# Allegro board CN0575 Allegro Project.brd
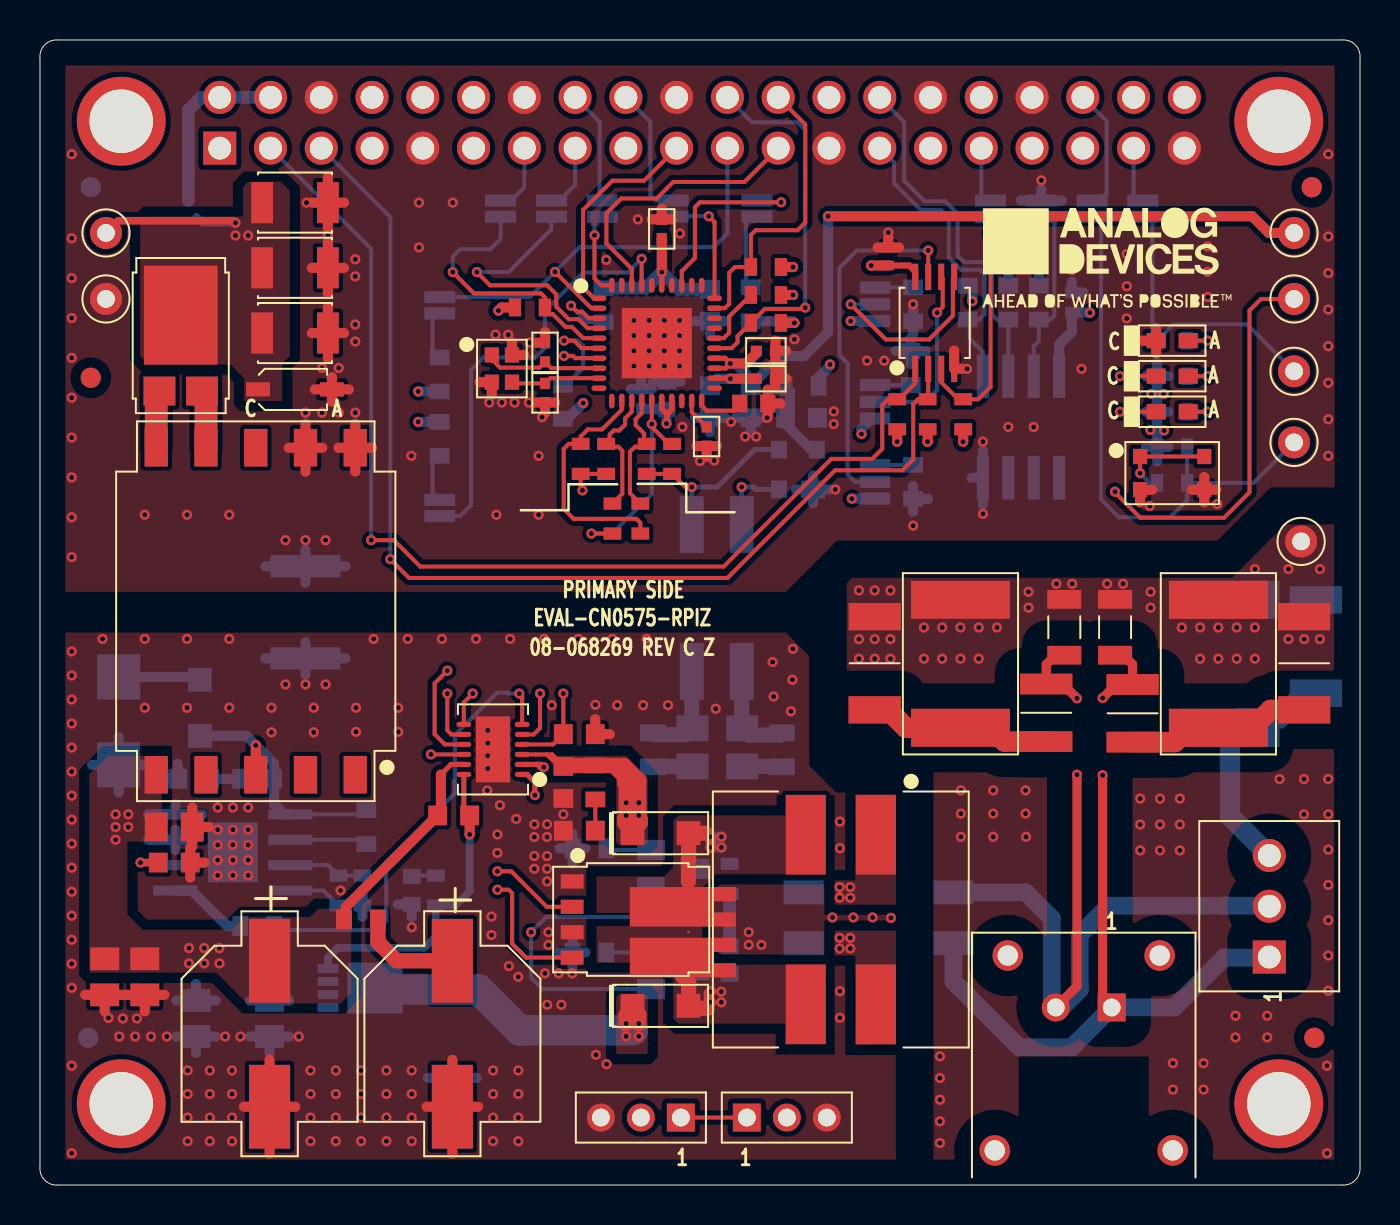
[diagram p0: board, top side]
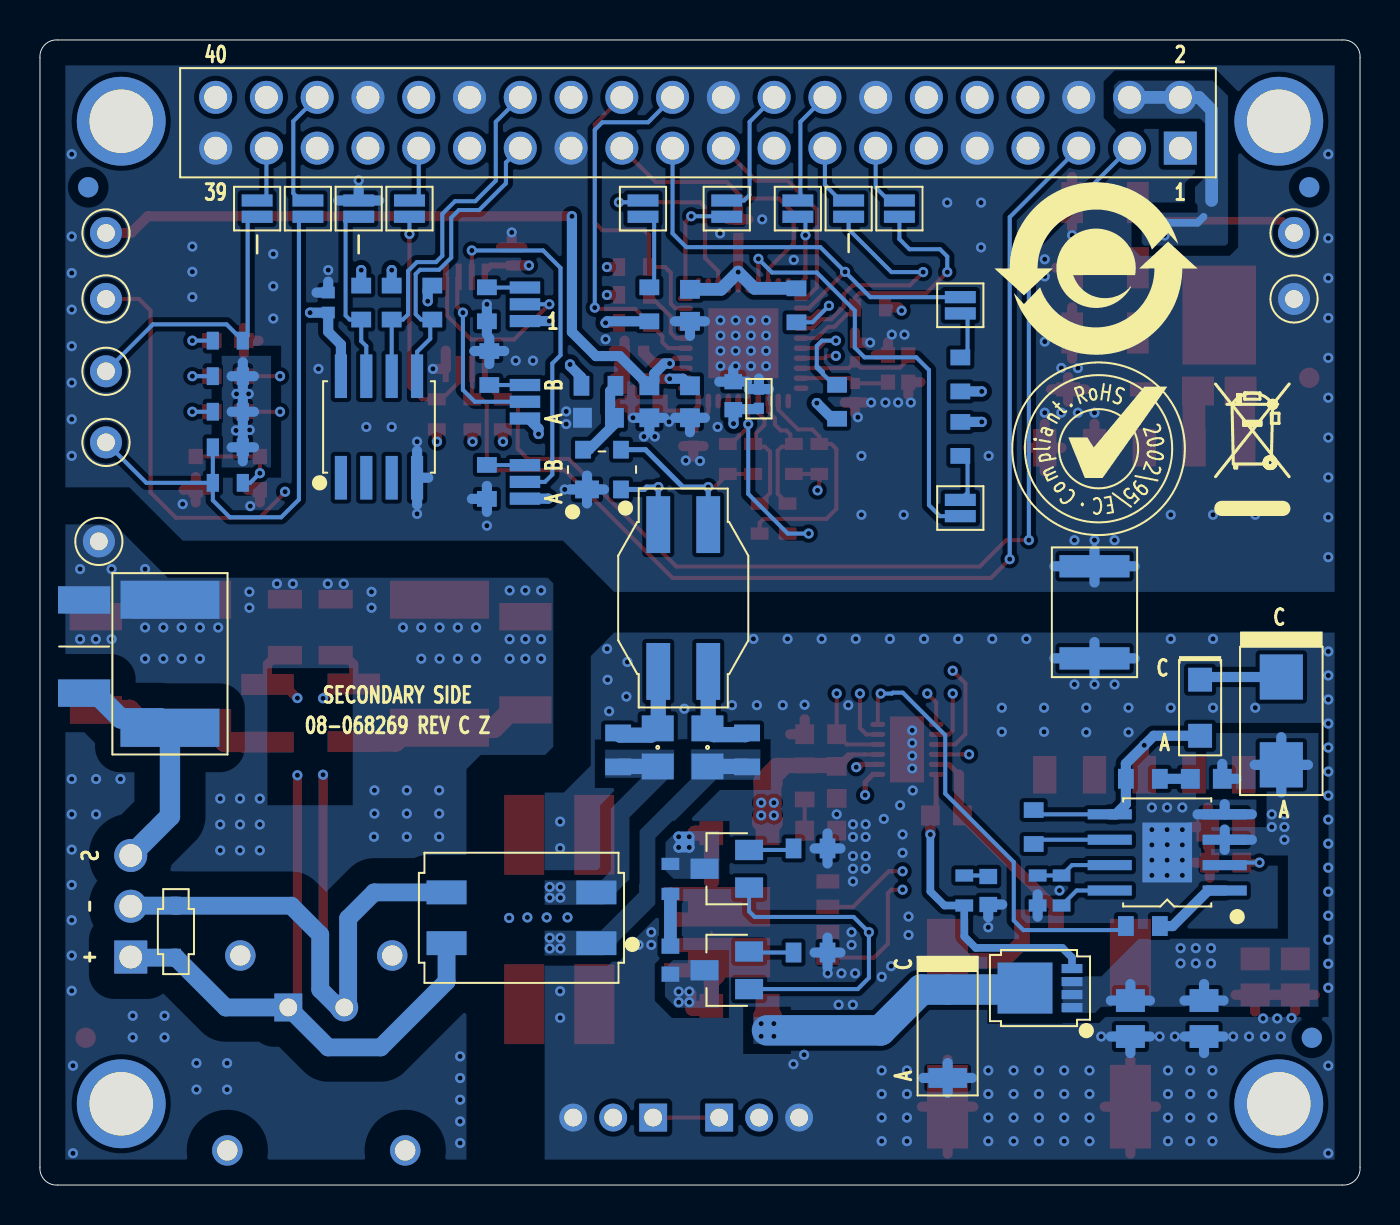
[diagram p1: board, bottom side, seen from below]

Outline 66.04 x 57.28 mm; copper layers: TOP, L2 GND, L3 PWR, BOTTOM. Coordinates in mm from the lower left corner of the outline.
Outline path: 0,56.39 arc(0.24,57.04) 0.89,57.28 65.15,57.28 arc(65.8,57.04) 66.04,56.39 66.04,0.89 arc(65.8,0.24) 65.15,0 0.89,0 arc(0.24,0.24) 0,0.89 0,56.39

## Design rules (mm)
constraint set DEFAULT: min track width 0.203

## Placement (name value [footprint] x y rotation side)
ALERT  APT1608LSECK/J3-PRV  [LED0603]  56.64 42.24 0 top
BTN_IO  TP_VIA  [TPC63D35]  62.74 37.15 270 top
C1  0.01UF  [C2220-2]  59.54 26.07 90 bottom
C2  0.22uF  [C0805H60]  32.65 21.89 90 bottom
C3  0.22uF  [C0805H60]  35.14 21.89 90 bottom
C4  100PF  [C1206]  53.79 27.9 90 top
C5  0.01UF  [C2220-2]  58.95 26.07 90 top
C6  0.01UF  [C2220-2]  46.05 26.07 90 top
C7  100PF  [C1206]  51.24 27.9 90 top
C8  0.1UF  [C0603]  38.1 38.38 0 bottom
C9  47NF  [C0603#2]  34.5 11.25 270 bottom
C10  0.22uF  [C0603]  26.98 17.73 180 top
C11  47NF  [C0603]  26.18 20.14 270 top
C12  22NF  [C0603#2]  18.6 14.73 270 bottom
C13  TBD0603  [C0603]  20.7 18.49 180 top
C14  4.7UF  [C0805H55]  11.49 8.33 270 bottom
C15  4.7UF  [C0805H55]  7.8 8.33 270 bottom
C16  47UF  [CPLSMSQ327H413]  20.63 7.57 270 top
C17  2.2uF  [C0603]  26.98 22.55 0 top
C18  22uF  [CPLSMSQ327H413]  11.49 7.57 270 top
C19  4.7UF  [C0805H55]  3.24 10.41 270 top
C20  4.7UF  [C0805H55]  5.25 10.41 270 top
C21  4.7UF  [C0805H55]  6.72 17.91 0 top
C22  270PF  [C0603]  7.69 20.32 0 bottom
C23  1UF  [C0603]  6.72 16.13 0 top
C24  4700pF  [C1812H79]  13.28 28.65 90 bottom
C25  100uF  [C1210H106]  12.76 49.14 0 top
C26  100uF  [C1210H106]  12.76 45.88 0 top
C27  100uF  [C1210H106]  12.76 42.62 0 top
C28  0.1uF  [C0402H22]  30.07 39.33 90 bottom
C29  0.01uF  [C0603#2]  31.36 39.48 90 bottom
C30  0.1uF  [C0402H22]  36.32 40.33 0 top
C31  0.01uF  [C0603]  33.52 39.18 270 bottom
C32  0.1uF  [C0402H22]  36.32 41.73 0 top
C33  680NF  [C0603]  35.55 39.18 270 bottom
C34  0.01uF  [C0603]  33.52 44.01 270 bottom
C35  0.1uF  [C0402H22]  31.11 47.82 90 top
C36  15PF  [C0402H22]  25.27 41.65 90 top
C37  15PF  [C0402H22]  25.27 39.62 270 top
C39  0.1uF  [C0402H22]  33.35 37.44 270 top
C40  1UF  [C0603#2]  35.71 39.09 0 top
C42  100NF  [C0402]  42.44 46.45 90 top
C43  100NF  [C0402]  51.62 44.14 90 bottom
CLKOUT  TP_VIA  [TPC63D35]  62.74 44.32 270 top
D1  D55V0M1B2WSQ-7  [SOD323_B]  59.24 12.67 90 bottom
D2  CD143A-SR05  [SOT143]  37.92 35.79 180 bottom
D3  PMEG10020AELRX  [SOD123F]  31.05 17.6 0 top
D4  PMEG10020AELRX  [SOD123F]  31.05 8.96 0 top
D5  PTVS58VP1UTP  [SOD128]  20.63 7.57 270 bottom
D6  824520511  [DO214AA_A]  3.94 23.22 270 bottom
D7  CMMR1U-02 TR  [SOD123F]  8 23.88 270 bottom
D8  PMEG045V100EPEZ  [SOT1289]  7.04 42.49 90 top
D9  CMHZ5232B TR  [SOD123-3]  12.76 39.8 0 top
EARTH  TP_VIA  [TPC63D35]  63.09 32.19 0 top
GND2  TP_VIA  [TPC63D35]  3.3 44.32 270 top
JP1  62000311121  [CNTHMHDR1X3L236W79H244]  35.36 3.37 0 top
JP2  62000311121  [CNTHMHDR1X3L236W79H244]  32.06 3.37 180 top
JP3  -  [JPSLD02]  35.87 48.84 270 bottom
JP4  -  [JPSLD02]  20 44.01 270 bottom
JP5  -  [JPSLD02]  20 33.86 90 bottom
JP6  3PIN_SOLDER_JUMPER  [JPRSLD03]  41.78 44.06 90 bottom
JP7  3PIN_SOLDER_JUMPER  [JPRSLD03]  41.78 39.18 90 bottom
JP8  3PIN_SOLDER_JUMPER  [JPRSLD03]  41.78 35.17 90 bottom
JP9  -  [JPSLD02]  23.04 48.84 90 bottom
JP10  -  [JPSLD02]  25.58 48.84 90 bottom
JP11  -  [JPSLD02]  28.12 48.84 270 bottom
JP12  -  [JPSLD02]  31.68 48.84 270 bottom
JP13  -  [JPSLD02]  47.56 48.84 90 bottom
JP14  -  [JPSLD02]  52.64 48.84 90 bottom
JP15  -  [JPSLD02]  55.18 48.84 270 bottom
JP16  -  [JPSLD02]  50.1 48.84 90 bottom
L1  470UH  [LSML236W362H209]  41.95 13.37 90 bottom
L2  220UH  [LSMSQ484H318]  40.06 13.28 180 top
L3  2200UH  [LSML280W236H189]  33.86 29.36 270 bottom
LED0  APT1608LZGCK  [LED0603]  56.64 40.46 0 top
LED1  APT1608LSECK/J4-PRV  [LED0603]  56.64 38.68 0 top
LED_IO  TP_VIA  [TPC63D35]  62.74 40.7 270 top
NOREF  -  []  65.87 0.31 0 top
NOREF#2  -  []  108.2 131.57 0 top
NOREF#3  -  []  -59.18 -70.36 0 top
NOREF#4  -  [unnamed#2]  61.98 53.21 0 top
NOREF#5  -  []  0 57.28 0 top
NOREF#6  -  []  0 0 0 top
NOREF#7  -  [unnamed#2]  2.54 40.38 0 top
NOREF#8  -  [unnamed#2]  61.98 4.06 0 top
NOREF#9  -  []  47.53 10 0 top
NOREF#10  -  [unnamed#2]  4.06 53.21 0 top
NOREF#11  -  []  66.04 57.28 180 top
NOREF#12  -  []  0.89 0 0 top
NOREF#13  -  []  0 57.28 270 top
NOREF#14  -  []  -3.3 284.73 0 top
NOREF#15  -  []  126.87 71.25 0 top
NOREF#16  -  []  0.89 57.28 0 top
NOREF#17  -  []  53.09 46.35 0 top
NOREF#18  -  []  66.04 0 90 top
NOREF#19  -  []  75.95 337.95 0 top
NOREF#20  -  [unnamed#2]  4.06 4.06 0 top
NOREF#21  -  [unnamed#2]  63.63 49.91 0 top
NOREF#22  -  []  0 0.89 0 top
NOREF#23  -  []  -139.95 -99.82 0 top
NOREF#24  -  []  4.06 4.06 0 top
NOREF#25  -  []  4.06 4.06 0 top
NOREF#26  -  []  116.39 73.1 0 top
NOREF#27  -  []  66.04 0 90 top
NOREF#28  -  []  44.83 97.41 0 top
NOREF#29  -  []  66.04 0.89 0 top
NOREF#30  -  [unnamed#2]  63.75 7.37 0 top
NOREF#31  -  []  -38.35 -37.34 0 top
NOREF#32  -  [unnamed#2]  63.63 49.91 180 bottom
NOREF#33  -  [unnamed#2]  2.41 7.37 180 bottom
NOREF#34  -  []  13.08 36.83 180 bottom
NOREF#35  -  []  13.21 45.85 180 bottom
NOREF#36  -  []  5.59 33.53 180 bottom
NOREF#37  -  [unnamed#2]  2.54 49.91 180 bottom
P1  691210910003  [CNWURTH691210910003]  61.5 11.4 90 top
P2  09452812810333  [CNHARTING09452812810333]  53.62 8.88 180 top
P3  SSQ-120-03-T-D  [CNTHFHDR2X20L2020W195H340]  8.99 51.87 0 bottom
Q1  BUK9M120-100EX  [SOT1210]  16.06 9.85 90 bottom
Q2  BSS123LT1G  [SOT23]  31.68 15.82 90 bottom
Q3  BSS123LT1G  [SOT23]  31.68 10.74 90 bottom
Q4  BUK9K134-100EX  [SOT1205]  29.9 13.28 270 top
R1  4.7MEG  [R2010]  63.83 26.94 90 bottom
R2  1K  [R1210]  54.66 23.6 270 top
R3  1K  [R1210]  50.34 23.62 270 top
R4  1MEG  [R0805]  30.66 21.76 90 bottom
R5  1MEG  [R0805]  37.12 21.76 90 bottom
R6  4.7MEG  [R2010]  63.25 26.1 90 top
R7  4.7MEG  [R2010]  41.76 26.1 90 top
R8  1K  [R0603]  38.1 39.98 180 bottom
R9  49.9  [R0603]  31.62 36.32 90 top
R10  5.1K  [R0603]  30.35 36.32 90 top
R11  49.9  [R0603]  27.05 36.32 90 top
R12  5.1K  [R0603]  28.32 36.32 90 top
R13  10.2K  [R0603]  28.64 33.34 90 top
R14  10.2K  [R0603]  30.04 33.34 270 top
R15  100  [R0603]  34.5 15.31 270 bottom
R16  40.2  [R0603]  27.78 20.14 270 top
R17  3.3  [R0603]  27.49 16.84 180 bottom
R18  3.3  [R0603]  27.49 11.63 180 bottom
R19  10K  [R0603]  19.8 14.73 90 bottom
R20  3.3  [R0603]  16.06 13.28 0 top
R21  10  [R0603]  10.86 12.95 0 bottom
R22  100K  [R0603]  14.93 14.73 90 bottom
R23  10K  [R0603]  16.13 14.73 270 bottom
R24  100  [R0603]  10.86 20.32 0 bottom
R25  316K  [R0603]  16.33 17.91 270 bottom
R26  4.7K  [R0603]  24.51 43.9 0 top
R27  1.5K  [R0603]  36.32 45.92 180 top
R28  1.5K  [R0603]  36.32 43.13 180 top
R29  1.5K  [R0603]  36.32 44.52 180 top
R30  324  [R0603]  56.64 40.46 0 bottom
R31  4.7K  [R0603]  28.19 44.01 270 bottom
R32  750  [R0603]  56.64 38.68 0 bottom
R33  4.7K  [R0603]  26.16 39.18 90 bottom
R34  4.7K  [R0603]  35.55 44.06 90 bottom
R35  4.7K  [R0603]  20 40.55 90 bottom
R36  4.7K  [R0603]  20 37.32 270 bottom
R37  10K  [R0603]  46.19 38.55 90 top
R38  10K  [R0603]  44.41 38.55 90 top
R39  10K  [R0603]  42.89 38.55 90 top
R40  10K  [R0603]  43.68 44.06 270 bottom
R41  10K  [R0603]  43.56 40.87 90 bottom
R42  10K  [R0603]  43.68 35.17 270 bottom
R43  3.9K  [R0603]  48.44 44.14 270 bottom
R44  3.9K  [R0603]  49.97 44.14 270 bottom
R45  3.9K  [R0603]  46.41 44.14 270 bottom
R46  10K  [R0603]  56.64 36.9 0 bottom
R47  249  [R0603]  56.64 35.12 180 bottom
R48  750  [R0603]  56.64 42.24 0 bottom
T1  750315125  [TSMSQ530H505]  10.79 28.7 180 top
TEST  PTS830 GM140 SMTR LFS  [SWSML102W120H59]  56.64 35.61 270 top
U1  LTC9111IDE#TRPBF  [DFN12_4X3_PAD3_3X1_7]  22.66 21.79 90 top
U2  LT8304HS8E-1#PBF  [SO8NB_PAD3X2_49]  9.65 16.64 90 bottom
U3  ADIN1110CCPZ  [QFN40_6X6_PAD3_5X3_5]  30.86 42.11 270 top
U4  ADT75BRMZ  [MSOP8]  44.76 43.13 0 top
U5  CAT24C32WI-GT3  [SO8]  49.08 37.92 180 bottom
UNK1.1V  TP_VIA  [TPC63D35]  62.74 47.62 270 top
UNK5V  TP_VIA  [TPC63D35]  3.3 47.62 270 bottom
Y1  25MEGHZ  [YSML79W63H20_A]  23.11 40.84 270 top

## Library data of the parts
ALERT = DIOLED: Tolerance: N/A; User Part Number: UPN; alternate symbols: (); part number: DIOLED_SM-APT1608LSECK/J3-PRV,1.8V,N/A,E030191,LED0603; tolerance: N/A
BTN_IO CLKOUT EARTH GND2 LED_IO UNK1.1V UNK5V = NCTESTPAD: Tolerance: N/A; User Part Number: UPN; alternate symbols: (); part number: NCTESTPAD_TH-TP_VIA,E012149,TPC63D35; tolerance: N/A
C1 C5 C6 = CAP: Tolerance: 10; User Part Number: UPN; alternate symbols: (); part number: CAP_SM-0.01UF,2000V,10,E048461,C2220-2; tolerance: 10
C2 C3 = CAP: Tolerance: 5; User Part Number: UPN; alternate symbols: (); part number: CAP_SM-0.22UF,100V,5,E018909,C0805H60; tolerance: 5
C4 C7 = CAP: User Part Number: UPN; Tolerance: 5; alternate symbols: (C1206L); part number: CAP_SM-100PF,2000V,5,E055826,C1206; tolerance: 5
C8 = CAP: User Part Number: UPN; Tolerance: 10; alternate symbols: (C0603L); part number: CAP_SM-0.1UF,100V,10,E048105,C0603; tolerance: 10
C9 C11 = CAP: User Part Number: UPN; Tolerance: 10; alternate symbols: (C0603L); part number: CAP_SM-47NF,100V,10,E058444,C0603; tolerance: 10
C10 = CAP: User Part Number: UPN; Tolerance: 10; alternate symbols: (C0603L); part number: CAP_SM-0.22UF,100V,10,E031432,C0603; tolerance: 10
C12 = CAP: User Part Number: UPN; Tolerance: 10; alternate symbols: (C0603L); part number: CAP_SM-22NF,100V,10,E043900,C0603; tolerance: 10
C13 = CAP: User Part Number: UPN; alternate symbols: (C0603L,C0603L_ALT); part number: CAP_SM-TBD0603,TBD0603,TBD0603,E000382,C0603
C14 C15 C19-C21 = CAP: User Part Number: UPN; Tolerance: 10; alternate symbols: (C0805L); part number: CAP_SM-4.7UF,100V,10,E057970,C0805H55; tolerance: 10
C16 = CAPP: User Part Number: UPN; Tolerance: 20; alternate symbols: (); part number: CAPP_SM-47UF,50V,20,E044727,CPLSMSQ327H413; tolerance: 20
C17 = CAP: User Part Number: UPN; Tolerance: 10; alternate symbols: (C0603L); part number: CAP_SM-2.2UF,25V,10,E031885,C0603; tolerance: 10
C18 = CAPP: User Part Number: UPN; Tolerance: 20; alternate symbols: (); part number: CAPP_SM-22UF,100V,20,E026358,CPLSMSQ327H413; tolerance: 20
C22 = CAP: User Part Number: UPN; Tolerance: 10; alternate symbols: (C0603L); part number: CAP_SM-270PF,100V,10,E052871,C0603; tolerance: 10
C23 C40 = CAP: User Part Number: UPN; Tolerance: 10; alternate symbols: (C0603L); part number: CAP_SM-1UF,25V,10,E048498,C0603; tolerance: 10
C24 = CAP: Tolerance: 10; User Part Number: UPN; alternate symbols: (); part number: CAP_SM-4700PF,2000V,10,E033725,C1812H79; tolerance: 10
C25-C27 = CAP: Tolerance: 20; User Part Number: UPN; alternate symbols: (); part number: CAP_SM-100UF,10V,20,E033226,C1210H106; tolerance: 20
C28 C30 C32 C35 C39 = CAP: Tolerance: 10; User Part Number: UPN; alternate symbols: (); part number: CAP_SM-0.1UF,16V,10,E026468,C0402H22; tolerance: 10
C29 C31 C34 = CAP: User Part Number: UPN; Tolerance: 10; alternate symbols: (C0603L); part number: CAP_SM-0.01UF,25V,10,E034502,C0603; tolerance: 10
C33 = CAP: User Part Number: UPN; Tolerance: 10; alternate symbols: (C0603L); part number: CAP_SM-680NF,10V,10,E058445,C0603; tolerance: 10
C36 C37 = CAP: Tolerance: 5; User Part Number: UPN; alternate symbols: (); part number: CAP_SM-15PF,50V,5,E054381,C0402H22; tolerance: 5
C42 C43 = CAP: User Part Number: UPN; Tolerance: 10; alternate symbols: (C0402L); part number: CAP_SM-100NF,25V,10,E058446,C0402; tolerance: 10
D1 = DIOZNR_V2: Tolerance: N/A; User Part Number: UPN; alternate symbols: (); part number: DIOZNR_V2_SM-D55V0M1B2WSQ-7,100V,N/A,E048935,SOD323_B; tolerance: N/A
D2 = DIO4P_V7: Tolerance: N/A; User Part Number: UPN; alternate symbols: (); part number: DIO4P_V7_SM-CD143A-SR05,5V,N/A,E019922,SOT143; tolerance: N/A
D3 D4 = DIOSCHOTTKY: Tolerance: N/A; User Part Number: UPN; alternate symbols: (); part number: DIOSCHOTTKY_SM-PMEG10020AELRX,100V,N/A,E035075,SOD123F; tolerance: N/A
D5 = DIOZNR: User Part Number: UPN; Tolerance: N/A; alternate symbols: (); part number: DIOZNR_SM-PTVS58VP1UTP,93.6V,N/A,E049291,SOD128; tolerance: N/A
D6 = DIOTVS: User Part Number: UPN; Tolerance: N/A; alternate symbols: (); part number: DIOTVS_SM-824520511,51V,N/A,E058447,DO214AA_A; tolerance: N/A
D7 = DIO: Tolerance: N/A; User Part Number: UPN; alternate symbols: (); part number: DIO_SM-CMMR1U-02 TR,200V,N/A,E029843,SOD123F; tolerance: N/A
D8 = DIOSCHOTTKY_3P: User Part Number: UPN; Tolerance: N/A; alternate symbols: (); part number: DIOSCHOTTKY_3P_SM-PMEG045V100EPEZ,45V,N/A,E059669,SOT1289; tolerance: N/A
D9 = DIOZNR: Tolerance: 5; User Part Number: UPN; alternate symbols: (); part number: DIOZNR_SM-CMHZ5232B TR,5.6V,5,E031187,SOD123-3; tolerance: 5
JP1 JP2 = CN3P: User Part Number: UPN; Tolerance: N/A; alternate symbols: (); part number: CN3P_TH-62000311121,E033291,CNTHMHDR1X3L236W79H244; tolerance: N/A
JP3-JP5 JP9-JP16 = NC2P: User Part Number: UPN; Tolerance: N/A; alternate symbols: (); part number: NC2P_SM-JPSLD02,E006230,JPSLD02; tolerance: N/A
JP6-JP8 = NC3P_JMPR: Tolerance: N/A; User Part Number: UPN; alternate symbols: (); part number: NC3P_JMPR_SM-3PIN_SOLDER_JUMPER,E005606,JPRSLD03; tolerance: N/A
L1 = CHOKE4P_V5: User Part Number: UPN; Tolerance: 50; alternate symbols: (); part number: CHOKE4P_V5_SM-470UH,50,E032119,LSML236W362H209; tolerance: 50
L2 = IND_4P_V4: Tolerance: 10; User Part Number: UPN; alternate symbols: (); part number: IND_4P_V4_SM-220UH,10,E014273,LSMSQ484H318; tolerance: 10
L3 = IND_4P_V16: User Part Number: UPN; Tolerance: 30; alternate symbols: (); part number: IND_4P_V16_SM-2200UH,30,E053387,LSML280W236H189; tolerance: 30
LED0 = DIOLED: Tolerance: N/A; User Part Number: UPN; alternate symbols: (); part number: DIOLED_SM-APT1608LZGCK,2.65V,N/A,E027397,LED0603; tolerance: N/A
LED1 = DIOLED: Tolerance: N/A; User Part Number: UPN; alternate symbols: (); part number: DIOLED_SM-APT1608LSECK/J4-PRV,1.8V,N/A,E057694,LED0603; tolerance: N/A
P1 = CN3P: User Part Number: UPN; Tolerance: N/A; alternate symbols: (); part number: CN3P_TH-691210910003,E058695,CNWURTH691210910003; tolerance: N/A
P2 = CN2P_4GND_V2: User Part Number: UPN; Tolerance: N/A; alternate symbols: (); part number: CN2P_4GND_V2_TH-09452812810333,E059670,CNHARTING09452812810333; tolerance: N/A
P3 = CN40P_V2: User Part Number: UPN; Tolerance: N/A; alternate symbols: (); part number: CN40P_V2_TH-SSQ-120-03-T-D,E033992,CNTHFHDR2X20L2020W195H340; tolerance: N/A
Q1 = TRANNMOSFET_V15: Tolerance: N/A; User Part Number: UPN; alternate symbols: (); part number: TRANNMOSFET_V15_SM-BUK9M120-100EX,E049297,SOT1210; tolerance: N/A
Q2 Q3 = TRANNMOSFET_V8: User Part Number: UPN; Tolerance: N/A; alternate symbols: (); part number: TRANNMOSFET_V8_SM-BSS123LT1G,E022331,SOT23; tolerance: N/A
Q4 = TRANNMOSFET_DUAL: Tolerance: N/A; User Part Number: UPN; alternate symbols: (); part number: TRANNMOSFET_DUAL_SM-BUK9K134-100EX,E047346,SOT1205; tolerance: N/A
R1 R6 R7 = RES: User Part Number: UPN; Tolerance: 5; alternate symbols: (R2010L); part number: RES_SM-4.7MEG,E031023,1/2W,5,R2010; tolerance: 5
R2 R3 = RES: User Part Number: UPN; Tolerance: 1; alternate symbols: (R1210L); part number: RES_SM-1K,E035927,3/4W,1,R1210; tolerance: 1
R4 R5 = RES: User Part Number: UPN; Tolerance: 1; alternate symbols: (R0805L); part number: RES_SM-1MEG,E003518,1/8W,1,R0805; tolerance: 1
R8 = RES: User Part Number: UPN; Tolerance: 1; alternate symbols: (R0603L); part number: RES_SM-1K,E003678,1/10W,1,R0603; tolerance: 1
R9 R11 = RES: User Part Number: UPN; Tolerance: 1; alternate symbols: (R0603L); part number: RES_SM-49.9,E003673,1/10W,1,R0603; tolerance: 1
R10 R12 = RES: User Part Number: UPN; Tolerance: 1; alternate symbols: (R0603L); part number: RES_SM-5.1K,E010098,1/10W,1,R0603; tolerance: 1
R13 R14 = RES: User Part Number: UPN; Tolerance: 1; alternate symbols: (R0603L); part number: RES_SM-10.2K,E013703,1/10W,1,R0603; tolerance: 1
R15 R24 = RES: User Part Number: UPN; Tolerance: 1; alternate symbols: (R0603L); part number: RES_SM-100,E003668,1/10W,1,R0603; tolerance: 1
R16 = RES: User Part Number: UPN; Tolerance: 0.1; alternate symbols: (R0603L); part number: RES_SM-40.2,E022643,3/8W,0.1,R0603; tolerance: 0.1
R17 R18 R20 = RES: User Part Number: UPN; Tolerance: 1; alternate symbols: (R0603L); part number: RES_SM-3.3,E057861,1/10W,1,R0603; tolerance: 1
R19 R23 R37-R42 R46 = RES: User Part Number: UPN; Tolerance: 1; alternate symbols: (R0603L); part number: RES_SM-10K,E003671,1/10W,1,R0603; tolerance: 1
R21 = RES: User Part Number: UPN; Tolerance: 1; alternate symbols: (R0603L); part number: RES_SM-10,E003666,1/10W,1,R0603; tolerance: 1
R22 = RES: User Part Number: UPN; Tolerance: 1; alternate symbols: (R0603L); part number: RES_SM-100K,E010279,1/10W,1,R0603; tolerance: 1
R25 = RES: User Part Number: UPN; Tolerance: 1; alternate symbols: (R0603L); part number: RES_SM-316K,E027926,1/10W,1,R0603; tolerance: 1
R26 R31 R33-R36 = RES: User Part Number: UPN; Tolerance: 5; alternate symbols: (R0603L); part number: RES_SM-4.7K,E031875,1/10W,5,R0603; tolerance: 5
R27-R29 = RES: User Part Number: UPN; Tolerance: 1; alternate symbols: (R0603L); part number: RES_SM-1.5K,E003704,1/10W,1,R0603; tolerance: 1
R30 = RES: User Part Number: UPN; Tolerance: 1; alternate symbols: (R0603L); part number: RES_SM-324,E004034,1/10W,1,R0603; tolerance: 1
R32 R48 = RES: User Part Number: UPN; Tolerance: 1; alternate symbols: (R0603L); part number: RES_SM-750,E029229,1/10W,1,R0603; tolerance: 1
R43-R45 = RES: User Part Number: UPN; Tolerance: 1; alternate symbols: (R0603L); part number: RES_SM-3.9K,E057974,1/10W,1,R0603; tolerance: 1
R47 = RES: User Part Number: UPN; Tolerance: 1; alternate symbols: (R0603L); part number: RES_SM-249,E003684,1/10W,1,R0603; tolerance: 1
T1 = XFMR10P_V16: User Part Number: UPN; Tolerance: N/A; alternate symbols: (); part number: XFMR10P_V16_SM-750315125,E043432,TSMSQ530H505; tolerance: N/A
TEST = SWSPST4P_V2: User Part Number: UPN; Tolerance: N/A; alternate symbols: (); part number: SWSPST4P_V2_SM-PTS830 GM140 SMTR LFS,E025176,SWSML102W120H59; tolerance: N/A
U1 = ADLTC9111: User Part Number: UPN; Tolerance: N/A; alternate symbols: (); part number: ADLTC9111_SM-LTC9111IDE#TRPBF,E047147,DFN12_4X3_PAD3_3X1_7; tolerance: N/A
U2 = LINLT8304: Tolerance: N/A; User Part Number: UPN; alternate symbols: (); part number: LINLT8304_SM-LT8304HS8E-1#PBF,E029541,SO8NB_PAD3X2_49; tolerance: N/A
U3 = ADIN1110_V2: User Part Number: UPN; Tolerance: N/A; alternate symbols: (); part number: ADIN1110_V2_SM-ADIN1110CCPZ,E049968,QFN40_6X6_PAD3_5X3_5; tolerance: N/A
U4 = ADT75: Tolerance: N/A; User Part Number: UPN; alternate symbols: (); part number: ADT75_SM-ADT75BRMZ,E029518,MSOP8; tolerance: N/A
U5 = CMOSCAT24CXX: Tolerance: N/A; User Part Number: UPN; alternate symbols: (); part number: CMOSCAT24CXX_SM-CAT24C32WI-GT3,E029939,SO8; tolerance: N/A
Y1 = XTAL4PIN_V3: Tolerance: 10ppm; User Part Number: UPN; alternate symbols: (); part number: XTAL4PIN_V3_SM-25MEGHZ,E056118,YSML79W63H20_A; tolerance: 10ppm

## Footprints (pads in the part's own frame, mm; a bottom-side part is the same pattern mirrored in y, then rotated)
C0402
  rect 0.483x0.559 smd: 1(-0.45,0) 2(0.45,0)
C0402H22
  rect 0.559x0.508 smd: 1(-0.479,0) 2(0.479,0)
C0603
  rect 0.94x0.991 smd: 1(-0.8,0) 2(0.8,0)
C0603#2
  rect 0.762x0.889 smd: 1(-0.7,0) 2(0.7,0)
C0805H55
  rect 1.143x1.448 smd: 1(-0.9,0) 2(0.9,0)
C0805H60
  rect 1.295x1.6 smd: 1(-0.953,0) 2(0.953,0)
C1206
  rect 0.94x1.702 smd: 1(-1.4,0) 2(1.4,0)
C1210H106
  rect 1.092x2.057 smd: 1(-1.646,0) 2(1.646,0)
C1812H79
  rect 1.118x3.505 smd: 1(-2.304,0) 2(2.304,0)
C2220-2
  rect 1.905x4.953 smd: 1(-3.202,0) 2(3.202,0)
CNHARTING09452812810333
  rect 1.397x1.397 hole 0.889: 1(0,0)
  round 1.397 hole 0.889: 2(2.8,0)
  round 1.524 hole 1.016: GND1(-2.4,-2.6) GND2(5.2,-2.6) GND3(5.85,7.15) GND4(-3.05,7.15)
CNTHFHDR2X20L2020W195H340
  rect 1.651x1.651 hole 1.143: 1(0,0)
  round 1.651 hole 1.143: 2(0,-2.54) 3(2.54,0) 4(2.54,-2.54) 5(5.08,0) 6(5.08,-2.54) 7(7.62,0) 8(7.62,-2.54) 9(10.16,0) 10(10.16,-2.54) 11(12.7,0) 12(12.7,-2.54) 13(15.24,0) 14(15.24,-2.54) 15(17.78,0) 16(17.78,-2.54) 17(20.32,0) 18(20.32,-2.54) 19(22.86,0) 20(22.86,-2.54) 21(25.4,0) 22(25.4,-2.54) 23(27.94,0) 24(27.94,-2.54) 25(30.48,0) 26(30.48,-2.54) 27(33.02,0) 28(33.02,-2.54) 29(35.56,0) 30(35.56,-2.54) 31(38.1,0) 32(38.1,-2.54) 33(40.64,0) 34(40.64,-2.54) 35(43.18,0) 36(43.18,-2.54) 37(45.72,0) 38(45.72,-2.54) 39(48.26,0) 40(48.26,-2.54)
CNTHMHDR1X3L236W79H244
  rect 1.397x1.397 hole 0.889: 1(0,0)
  round 1.397 hole 0.889: 2(2,0) 3(4,0)
CNWURTH691210910003
  rect 1.651x1.651 hole 1.143: 1(0,0)
  round 1.651 hole 1.143: 2(2.54,0) 3(5.08,0)
CPLSMSQ327H413
  rect 4.191x2.057 smd: N(3.65,0) P(-3.65,0)
DFN12_4X3_PAD3_3X1_7
  oval 0.254x0.737 smd: 1(-1.25,-1.46) 2(-0.75,-1.46) 3(-0.25,-1.46) 4(0.25,-1.46) 5(0.75,-1.46) 6(1.25,-1.46) 7(1.25,1.46) 8(0.75,1.46) 9(0.25,1.46) 10(-0.25,1.46) 11(-0.75,1.46) 12(-1.25,1.46)
  rect 3.302x1.702 smd: PAD(0,0)
DO214AA_A
  rect 2.261x2.159 smd: A(2.197,0) C(-2.197,0)
JPRSLD03
  rect 0.61x1.524 smd: 1(-0.838,0) 2(0,0) 3(0.838,0)
JPSLD02
  rect 0.61x1.549 smd: 1(-0.406,0) 2(0.406,0)
LED0603
  rect 0.965x0.762 smd: A(0.8,0) C(-0.8,0)
LSML236W362H209
  rect 1.194x2.007 smd: 1(-1.27,-3.747) 2(1.27,-3.747) 3(1.27,3.747) 4(-1.27,3.747)
LSML280W236H189
  rect 2.845x1.194 smd: 1(-3.672,-1.25) 2(3.672,-1.25) 3(3.672,1.25) 4(-3.672,1.25)
LSMSQ484H318
  rect 2.007x3.988 smd: 1(-1.753,-4.242) 2(1.753,-4.242) 3(1.753,4.242) 4(-1.753,4.242)
MSOP8
  rect 0.305x1.321 smd: 1(-0.975,-2.3) 2(-0.325,-2.3) 3(0.325,-2.3) 4(0.975,-2.3) 5(0.975,2.3) 6(0.325,2.3) 7(-0.325,2.3) 8(-0.975,2.3)
QFN40_6X6_PAD3_5X3_5
  oval 0.279x0.737 smd: 1(-2.25,-2.893) 2(-1.75,-2.893) 3(-1.25,-2.893) 4(-0.75,-2.893) 5(-0.25,-2.893) 6(0.25,-2.893) 7(0.75,-2.893) 8(1.25,-2.893) 9(1.75,-2.893) 10(2.25,-2.893) 21(2.25,2.893) 22(1.75,2.893) 23(1.25,2.893) 24(0.75,2.893) 25(0.25,2.893) 26(-0.25,2.893) 27(-0.75,2.893) 28(-1.25,2.893) 29(-1.75,2.893) 30(-2.25,2.893)
  oval 0.737x0.279 smd: 11(2.893,-2.25) 12(2.893,-1.75) 13(2.893,-1.25) 14(2.893,-0.75) 15(2.893,-0.25) 16(2.893,0.25) 17(2.893,0.75) 18(2.893,1.25) 19(2.893,1.75) 20(2.893,2.25) 31(-2.893,2.25) 32(-2.893,1.75) 33(-2.893,1.25) 34(-2.893,0.75) 35(-2.893,0.25) 36(-2.893,-0.25) 37(-2.893,-0.75) 38(-2.893,-1.25) 39(-2.893,-1.75) 40(-2.893,-2.25)
  rect 3.505x3.505 smd: PAD(0,0)
R0603
  rect 0.61x0.889 smd: 1(-0.75,0) 2(0.75,0)
R0805
  rect 0.838x1.295 smd: 1(-0.85,0) 2(0.85,0)
R1210
  rect 1.041x2.616 smd: 1(-1.441,0) 2(1.441,0)
R2010
  rect 1.372x2.616 smd: 1(-2.331,0) 2(2.331,0)
SO8
  rect 0.61x2.184 smd: 1(-1.905,-2.54) 2(-0.635,-2.54) 3(0.635,-2.54) 4(1.905,-2.54) 5(1.905,2.54) 6(0.635,2.54) 7(-0.635,2.54) 8(-1.905,2.54)
SO8NB_PAD3X2_49
  rect 0.508x2.21 smd: 1(-1.905,-2.875) 2(-0.635,-2.875) 3(0.635,-2.875) 4(1.905,-2.875) 5(1.905,2.875) 6(0.635,2.875) 7(-0.635,2.875) 8(-1.905,2.875)
  rect 2.997x2.489 smd: PAD(0,0)
SOD123-3
  rect 1.194x0.711 smd: A(1.847,0) C(-1.847,0)
SOD123F
  rect 1.194x1.194 smd: A(1.403,0) C(-1.403,0)
SOD128
  rect 0.991x1.93 smd: A(2.21,0) C(-2.21,0)
SOD323_B
  rect 0.889x0.508 smd: 1(-1.3,0) 2(1.3,0)
SOT23
  rect 1.016x1.397 smd: 1(-0.94,-1.118) 2(0.94,-1.118) 3(0,1.118)
SOT143
  rect 1.194x0.889 smd: 1(-0.75,-0.994)
  rect 0.787x0.889 smd: 2(0.95,-0.994) 3(0.95,0.994) 4(-0.95,0.994)
SOT1205
  rect 0.711x1.143 smd: 1(-1.905,-3.278) 2(-0.635,-3.278) 3(0.635,-3.278) 4(1.905,-3.278)
  custom 0.495x0.495 smd: 5(1.905,2.26) 7(-0.635,2.26)
  round 0.127 smd: 6(0.635,2.54) 8(-1.905,2.54)
SOT1210
  rect 0.457x1.041 smd: 1(-0.975,-1.65) 2(-0.325,-1.65) 3(0.325,-1.65) 4(0.975,-1.65)
  round 0.127 smd: 5(0.975,1.65) 6(0.325,1.65) 7(-0.325,1.65) 8(-0.975,1.65)
SOT1289
  rect 1.448x1.6 smd: 1(-2.776,-1.065) 2(-2.776,1.065)
  rect 4.953x3.683 smd: 3(1.024,0)
SWSML102W120H59
  rect 0.762x0.711 smd: 1(-0.831,-1.606) 2(-0.831,1.606) 3(0.831,-1.606) 4(0.831,1.606)
TPC63D35
  round 1.6 hole 0.889: 1(0,0)
TSMSQ530H505
  rect 1.168x1.88 smd: 1(-4.978,8.179) 2(-2.489,8.179) 3(0,8.179) 4(2.489,8.179) 5(4.978,8.179) 6(4.978,-8.179) 7(2.489,-8.179) 8(0,-8.179) 9(-2.489,-8.179) 10(-4.978,-8.179)
unnamed#2
  round 4.445 hole 3.175 unplated: (0,0)
YSML79W63H20_A
  rect 0.762x0.711 smd: 1(-0.681,-0.506) 2(0.681,-0.506) 3(0.681,0.506) 4(-0.681,0.506)

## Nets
3V3_POWER: C28.1 C29.1 C30.1 C31.1 C34.1 C35.1 C42.1 C43.1 JP6.1 JP7.1 JP8.1 P3.1 P3.17 R8.1 R26.1 R27.1 R28.1 R29.1 R30.1 R31.1 R32.1 R33.1 R34.1 R35.1 R36.1 R37.1 R38.1 R39.1 R43.1 R44.1 R45.1 R46.1 U3.16 U3.17 U3.22 U3.35 U4.8(VDD) U5.8
5V_POWER: C25.1 C26.1 C27.1 D8.3(C) D9.C P3.2 P3.4 UNK5V.1
GND: C10.2(N2) C11.2(N2) C12.2(N2) C14.2(N2) C15.2(N2) C16.N(N2) C17.2(N2) C18.N(N2) C19.2(N2) C20.2(N2) C21.2(N2) C23.2(N2) C24.1 D5.A(P) JP1.3(N3) JP2.3(N3) Q4.1 Q4.3(S) R17.2(N2) R18.2(N2) R23.2(N2) U1.PAD U2.4 U2.PAD
GND_EARTH: C1.2(N2) C4.2(N2) C5.2(N2) C6.2(N2) C7.2(N2) EARTH.1(N1) R1.2(N2) R6.2(N2) R7.2(N2)
GND_ISO: ALERT.C C8.2(N2) C24.2(N2) C25.2(N2) C26.2(N2) C27.2(N2) C28.2(N2) C29.2(N2) C30.2(N2) C31.2(N2) C32.2(N2) C33.2(N2) C34.2(N2) C35.2(N2) C36.2(N2) C37.2(N2) C39.2(N2) C40.2(N2) C42.2(N2) C43.2(N2) D2.1 D9.A(P) GND2.1(N1) JP16.2(N2) P3.6 P3.9 P3.14 P3.20 P3.25 P3.30 P3.34 P3.39 R40.2(N2) R41.2(N2) R42.2(N2) T1.9 T1.10 TEST.3 TEST.4(N4) U3.PAD U4.4 U5.4 Y1.2 Y1.4
ADT75_OS: JP13.1 R37.2(N2) U4.3
BUTTON_IO: BTN_IO.1(N1) JP14.1 R46.2(N2) R47.1
CS_N: P3.24 R27.2(N2) U3.29
DIFF_N: C3.1 L1.2 L2.1 R5.1
DIFF_P: C2.1 L1.1 L2.4(N4) R4.1
EEPROM_SCL: P3.28 R43.2(N2) U5.6
EEPROM_SDA: P3.27 R45.2(N2) U5.5
I2C_SCL: P3.5 R38.2(N2) U4.2
I2C_SDA: P3.3 R39.2(N2) U4.1
INT_N: P3.22 R28.2(N2) U3.25
LED_IO: JP15.2(N2) LED_IO.1(N1) R48.1
LINK_ST: JP10.1 U3.4
LT8304_EN: R21.1 U2.1
LT8304_VIN: C13.2(N2) C14.1 C15.1 C18.P C19.1 C20.1 C21.1 C22.1 D6.A(P) Q1.1 Q1.2 Q1.3(S3) R20.1 T1.5 U1.11 U2.3(VIN)
LTC9111_STBY: C17.1 JP1.1 JP2.1 U1.4
PD_IN1: D3.A(P) L2.2 Q2.3 Q4.7 Q4.8 R15.1 U1.1
PD_IN2: C9.2(N2) D4.A(P) L2.3 Q3.3 Q4.5 Q4.6 U1.2(VSNS2)
RESET_N: JP9.1 R26.2(N2) U3.5
RXN: R12.2(N2) R13.2(N2) U3.13
RXP: R10.2(N2) R14.1 U3.14
SCLK: P3.23 U3.38
SDI: P3.19 U3.1
SDO/SPI_CFG0: JP4.1 P3.21 U3.2
SPI_CFG1: JP5.1 U3.37
SWPD_ENB: JP3.1 U3.33
TS_CAPT: JP11.2(N2) U3.40
TS_TIMER/MS_SEL: JP12.2(N2) U3.30
TVS_VCC: C8.1 D2.4(REF) R8.2(N2)
TXN: R11.2(N2) R14.2(N2) U3.12
TXP: R9.2(N2) R13.1 U3.15
UNNAMED_3_CAP_I52_N2: C22.2(N2) R24.1
UNNAMED_3_CAP_I56_N1: C23.1 U2.2
UNNAMED_3_DIO_I55_N: D6.C D7.C
UNNAMED_3_DIO_I55_P: D7.A(P) R24.2(N2) R25.1 T1.3 U2.5
UNNAMED_3_DIOSCHOTTKY3P_I49_A1: D8.1 T1.7
UNNAMED_3_DIOSCHOTTKY3P_I49_A2: D8.2 T1.6
UNNAMED_3_LINLT8304_I62_RFB: R25.2(N2) U2.6
UNNAMED_3_LINLT8304_I62_RREF: R22.2(N2) R23.1 U2.7
UNNAMED_3_LINLT8304_I62_TC: R22.1 U2.8
UNNAMED_6_CMOSCAT24CXX_I92_WP: JP16.1 R44.2(N2) U5.7(WP)
UNNAMED_6_CN40PV2_I2_N8: JP11.1 P3.16
UNNAMED_6_CN40PV2_I2_N9: JP12.1 P3.18(N9)
UNNAMED_6_CN40PV2_I2_N18: JP14.2(N2) P3.36
UNNAMED_6_CN40PV2_I3_N7: JP9.2(N2) P3.13
UNNAMED_6_CN40PV2_I3_N8: JP10.2(N2) P3.15
UNNAMED_6_CN40PV2_I3_N16: JP13.2(N2) P3.31
UNNAMED_6_CN40PV2_I3_N19: JP15.1 P3.37
UNNAMED_6_DIOLED_I156_P: ALERT.A(P) R48.2(N2)
UNNAMED_6_RES_I163_N2: R47.2(N2) TEST.1 TEST.2
UNNAMED_8_CAP_I59_N2: C2.2(N2) L3.3 R4.2(N2)
UNNAMED_8_CAP_I60_N2: C3.2(N2) L3.2 R5.2(N2)
UNNAMED_8_CAP_I64_N1: C4.1 D1.1 L1.4(N4) P1.1 P2.1 R2.1
UNNAMED_8_CAP_I66_N1: C5.1 R2.2(N2) R6.1
UNNAMED_8_CAP_I70_N1: C6.1 R3.2(N2) R7.1
UNNAMED_8_CAP_I71_N1: C7.1 D1.2(N2) L1.3 P1.2 P2.2 R3.1
UNNAMED_8_CAP_I91_N1: C1.1 P1.3(N3) P2.GND1 P2.GND2 P2.GND3 P2.GND4(N6) R1.1
UNNAMED_8_DIO4PV7_I21_I: D2.2 L3.1 R11.1 R12.1
UNNAMED_8_DIO4PV7_I21_I_1: D2.3 L3.4(N4) R9.1 R10.1
UNNAMED_9_ADLTC9111_I40_CLASSC: JP2.2 U1.10
UNNAMED_9_ADLTC9111_I40_CLASSV: JP1.2 U1.5
UNNAMED_9_ADLTC9111_I40_EN: R21.2(N2) U1.6
UNNAMED_9_ADLTC9111_I40_GATE: C13.1 Q1.4 R19.1 U1.12
UNNAMED_9_ADLTC9111_I40_LGATE1: Q4.2 U1.9
UNNAMED_9_ADLTC9111_I40_LGATE2: Q4.4 U1.8
UNNAMED_9_ADLTC9111_I40_SCCP: Q2.1 Q3.1 U1.7
UNNAMED_9_CAP_I53_N1: C10.1 R16.2(N2)
UNNAMED_9_CAP_I54_N1: C9.1 R15.2(N2)
UNNAMED_9_CAP_I80_N1: C12.1 R19.2(N2)
UNNAMED_9_CAPP_I72_N1: C16.P R20.2(N2)
UNNAMED_9_RES_I96_N1: Q2.2(S) R17.1
UNNAMED_9_RES_I97_N1: Q3.2(S) R18.1
UNNAMED_10_ADIN1110V2_I97_CEXT2: C39.1 U3.19
UNNAMED_10_ADIN1110V2_I97_CEXT3: C40.1 U3.20
UNNAMED_10_ADIN1110V2_I97_CLK25REF: CLKOUT.1(N1) U3.7
UNNAMED_10_ADIN1110V2_I97_DLDO1P1: C32.1 C33.1 U3.23 U3.24 UNK1.1V.1
UNNAMED_10_ADIN1110V2_I97_LED0: LED0.C R31.2(N2) U3.3
UNNAMED_10_ADIN1110V2_I97_LED1: LED1.C R33.2(N2) U3.6
UNNAMED_10_ADIN1110V2_I97_TEST1: R29.2(N2) U3.26
UNNAMED_10_DIOLED_I154_P: LED0.A(P) R30.2(N2)
UNNAMED_10_DIOLED_I156_P: LED1.A(P) R32.2(N2)
UNNAMED_10_NC2P_I58_N2: JP3.2(N2) R34.2(N2)
UNNAMED_10_NC2P_I158_N2: JP4.2(N2) R35.2(N2)
UNNAMED_10_NC2P_I159_N2: JP5.2(N2) R36.2(N2)
UNNAMED_11_ADT75_I4_A0: JP8.2(COM) U4.7
UNNAMED_11_ADT75_I4_A1: JP7.2(COM) U4.6
UNNAMED_11_ADT75_I4_A2: JP6.2(COM) U4.5
UNNAMED_11_NC3PJMPR_I11_B: JP8.3 R42.1
UNNAMED_11_NC3PJMPR_I12_B: JP7.3 R41.1
UNNAMED_11_NC3PJMPR_I13_B: JP6.3 R40.1
VPD: C11.1 D3.C D4.C D5.C Q1.5 Q1.6 Q1.7 Q1.8 R16.1 U1.3
XTALI: C36.1 U3.8 Y1.1
XTALO: C37.1 U3.9(XTAL_O) Y1.3(N2)

Pads without a net: P3 7 8 10 11 12 26 29 32 33 35 38 40; T1 1 2 4 8; U3 10 11 18 21 27 28 31 32 34 36 39; U5 1 2 3

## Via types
v1: diameter 0.508, hole 0.254, TOP to BOTTOM, 465 vias

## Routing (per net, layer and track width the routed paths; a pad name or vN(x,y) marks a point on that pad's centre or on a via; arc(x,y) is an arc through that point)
3V3_POWER: length 47.8
  TOP w0.254: v1(31.11,45.67) 31.11,45.66 U3.35
  TOP w0.279: v1(31.34,38.09) 31.34,38.19 31.37,38.21 31.37,38.54 ; U3.16 31.11,38.81 31.37,38.54 ; 31.37,38.54 31.61,38.78 U3.17 ; U3.22 34.51,40.36 v1(34.54,40.33)
  TOP w0.305: U4.8 43.79,45.69 43.48,46 C42.1
  TOP w0.508: v1(42.88,37.19) 42.89,37.2 R39.1 ; v1(44.4,37.19) 44.41,37.2 R38.1 ; v1(46.18,37.19) 46.19,37.2 R37.1 ; R27.1 v1(37.68,45.92) ; C30.1 v1(34.54,40.33) ; v1(31.11,45.67) 31.11,47.34 C35.1 ; v1(41.58,46) C42.1 ; R29.1 v1(37.68,44.52) ; R26.1 23.09,43.9 v1(22.94,43.74) ; R28.1 v1(37.74,43.13)
  BOTTOM w0.508: R32.1 55.89,39.38 ; R32.1 56.45,38.68 ; R32.1 55.89,37.98 ; R32.1 55.33,38.68 ; v1(39.52,41.05) 39.52,40.97 38.95,40.4 R8.1 ; R43.1 v1(48.44,45.77) ; JP6.1 v1(40.56,43.22) ; 55.89,39.76 R30.1 ; R30.1 55.33,40.46 ; R30.1 56.45,40.46 ; R30.1 55.89,41.16 ; v1(41.1,37.57) 41.1,37.83 41.61,38.34 JP7.1 ; v1(52.53,43.64) 51.62,43.64 C43.1 51.62,42.68 50.98,42.04 U5.8 ; v1(18.92,39.7) R35.1 ; JP8.1 v1(40.61,34.33) ; R34.1 37.66,43.21 v1(37.74,43.13) ; R33.1 26.39,38.33 v1(27.18,39.12) ; C31.1 33.87,40.33 v1(34.54,40.33) ; 55.33,36.9 R46.1 ; R46.1 55.89,37.6 ; R46.1 55.89,36.2 ; R46.1 56.45,36.9 ; v1(31.34,38.09) 31.34,38.77 C29.1 31.33,38.81 30.12,38.81 C28.1 ; R45.1 46.64,44.76 v1(46.64,44.21) ; R44.1 v1(49.97,45.77) ; v1(18.92,38.17) R36.1
  BOTTOM w0.635: R31.1 30.3,44.86 v1(31.11,45.67) 31.97,44.81 C34.1
  vias: v1(55.6,39.57) v1(55.55,37.77) v1(56.21,39.57) v1(56.24,37.74)
5V_POWER: length 17.7
  TOP w0.381: UNK5V.1 3.91,48.23 9.68,48.23 v1(9.78,48.13)
  BOTTOM w0.381: v1(9.78,48.13) 8.13,48.13 7.83,48.43
  BOTTOM w0.635: P3.4 P3.2 8.06,54.41 7.42,53.77 7.42,49.25
  vias: v1(9.78,47.5) v1(10.41,47.5)
GND: length 53
  TOP w0.508: C18.N 12.77,3.92 ; C18.N 11.49,1.57 ; C18.N 11.49,6.27 ; C18.N 10.2,3.92 ; 5.25,8.69 C20.2 ; C20.2 4.27,9.51 ; C20.2 6.22,9.51 ; 27.78,23.3 C17.2 28.51,22.55 ; 20.63,1.57 C16.N ; C16.N 20.63,6.27 ; C16.N 19.35,3.92 ; C16.N 21.91,3.92 ; 3.24,8.69 C19.2 ; C19.2 4.22,9.51 ; C19.2 2.26,9.51 ; C21.2 8.44,17.91 ; C21.2 7.62,18.89 ; C21.2 7.62,16.93 ; C23.2 7.52,16.88 ; C23.2 8.24,16.13 ; C23.2 7.52,15.38
  BOTTOM w0.508: C15.2 8.78,7.43 ; C15.2 6.83,7.43 ; C15.2 7.8,6.6 ; 17.9,14.03 C12.2 18.6,13.4 ; 25.99,16.84 R17.2 ; R17.2 27.29,16.84 ; R17.2 26.64,16.09 ; R17.2 26.64,17.59 ; 26.64,10.88 R18.2 ; R18.2 26.64,12.38 ; R18.2 25.99,11.63 ; R18.2 27.29,11.63 ; 10.51,7.43 C14.2 ; C14.2 11.49,6.6 ; C14.2 12.47,7.43 ; D5.A 20.63,6.11 ; D5.A 21.85,5.36 ; D5.A 19.41,5.36 ; D5.A 20.63,4.61 ; 5.41,18.54 U2.4 ; U2.4 8.13,18.54 ; U2.4 6.77,19.05 ; 13.28,25.53 C24.1 ; C24.1 15.29,26.34 ; C24.1 11.28,26.34 ; C24.1 13.28,27.16 ; 16.13,14.54 R23.2 16.13,13.42
  vias: v1(1.59,26.69) v1(1.59,25.49) v1(1.59,24.29) v1(1.59,23.08) v1(1.59,21.88) v1(1.59,20.68) v1(1.59,19.48) v1(1.59,18.28) v1(1.59,17.08) v1(1.59,15.87) v1(1.59,14.67) v1(1.59,13.47) v1(1.59,12.27) v1(1.59,11.07) v1(1.59,9.87) v1(1.59,5.97) v1(1.59,1.59) v1(3.13,27.32) v1(3.43,8.36) v1(3.97,7.43) v1(4.14,8.33) v1(4.76,7.43) v1(4.85,8.33) v1(5.24,27.32) v1(5.24,23.88) v1(5.55,7.43) v1(6.34,7.43) v1(7.36,27.32) v1(7.36,23.88) v1(7.39,5.73) v1(7.39,4.55) v1(7.39,3.37) v1(7.39,2.19) v1(8.5,5.73) v1(8.5,4.55) v1(8.5,3.37) v1(8.5,2.19) v1(8.89,18.88) v1(8.89,17.78) v1(8.89,17.01) v1(8.89,16.25) v1(8.89,15.49) v1(9.26,7.43) v1(9.47,27.32) v1(9.47,23.88) v1(9.61,5.73) v1(9.61,4.55) v1(9.61,3.37) v1(9.61,2.19) v1(9.65,18.88) v1(9.65,17.78) v1(9.65,17.02) v1(9.65,16.25) v1(9.65,15.49) v1(10.03,7.43) v1(10.41,18.88) v1(10.41,17.78) v1(10.41,17.01) v1(10.41,16.25) v1(10.41,15.49) v1(11.58,23.88) v1(11.58,22.64) v1(12.28,25.04) v1(12.95,7.43) v1(13.28,25.04) v1(13.53,5.73) v1(13.53,4.55) v1(13.53,3.37) v1(13.53,2.19) v1(13.7,23.88) v1(13.7,22.64) v1(14.29,25.04) v1(14.8,5.73) v1(14.8,4.55) v1(14.8,3.37) v1(14.8,2.19) v1(15.04,14.73) v1(15.81,23.88) v1(15.81,22.67) v1(16.07,5.73) v1(16.07,4.55) v1(16.07,3.37) v1(16.07,2.19) v1(16.69,27.32) v1(17.33,5.73) v1(17.33,4.55) v1(17.33,3.37) v1(17.33,2.19) v1(17.92,23.88) v1(17.92,22.67) v1(18.4,27.32) v1(18.6,12.89) v1(18.6,5.73) v1(18.6,4.55) v1(18.6,3.37) v1(18.6,2.19) v1(20.11,27.32) v1(21.81,27.32) v1(22.4,22.74) v1(22.4,22.11) v1(22.4,21.47) v1(22.4,20.84) v1(22.38,19.74) v1(22.59,13.43) v1(22.59,12.51) v1(22.67,5.73) v1(22.67,4.55) v1(22.67,3.37) v1(22.67,2.19) v1(22.89,17.54) v1(22.89,16.62) v1(23.01,19) v1(23.46,10.95) v1(23.52,27.32) v1(23.83,18.31) v1(23.93,10.41) v1(23.93,5.73) v1(23.93,4.55) v1(23.93,3.37) v1(23.93,2.19) v1(24.73,18.04) v1(24.73,17.41) v1(24.73,16.46) v1(24.73,15.82) v1(25.23,27.32) v1(25.26,10.59) v1(25.37,18.04) v1(25.37,17.41) v1(25.37,16.46) v1(25.37,15.82) v1(25.37,15.19) v1(25.37,9.02) v1(25.44,12.65) v1(25.44,12.01) v1(25.6,24) v1(25.95,10.59) v1(26.09,9.02) v1(26.18,18.54) v1(26.63,10.59) v1(26.93,27.32) v1(27.79,24.03) v1(27.81,6.52) v1(28.35,6.04) v1(28.64,27.32) v1(28.88,24) v1(30.18,24) v1(30.35,27.32) v1(31.42,24) v1(33.81,23.83) v1(35.46,12.65) v1(35.46,12.01) v1(36.09,12.01) v1(36.65,26.16) v1(36.7,24.43) v1(37.57,23.7) v1(37.67,26.82) v1(37.64,25.27) v1(39.65,13.39) v1(40.02,18.18) v1(40.02,16.85) v1(40.02,9.69) v1(40.02,8.36) v1(40.69,13.39) v1(41.66,13.39) v1(42.57,13.36)
GND_EARTH:
  vias: v1(40.97,29.74) v1(40.97,27.31) v1(40.97,26.33) v1(41.76,29.74) v1(41.76,27.31) v1(41.76,26.33) v1(42.55,29.74) v1(42.55,27.31) v1(42.55,26.33) v1(44.22,27.89) v1(44.22,26.33) v1(45.02,6.43) v1(45.02,5.35) v1(45.02,4.27) v1(45.02,3.18) v1(45.02,2.1) v1(45.14,27.89) v1(45.14,26.33) v1(46.05,27.89) v1(46.05,26.33) v1(46.07,19.74) v1(46.07,18.58) v1(46.07,17.42) v1(46.96,27.89) v1(46.96,26.33) v1(47.69,19.74) v1(47.69,18.58) v1(47.69,17.42) v1(47.88,27.89) v1(49.31,19.74) v1(49.31,18.58) v1(49.33,17.42) v1(49.45,29.67) v1(49.45,28.88) v1(50.85,30.07) v1(51.64,30.07) v1(53.39,30.07) v1(54.19,30.07) v1(55.04,19.33) v1(55.04,18.03) v1(55.04,16.74) v1(55.56,29.67) v1(55.56,28.88) v1(56.03,19.33) v1(56.03,18.03) v1(56.03,16.74) v1(56.68,6.1) v1(56.68,4.78) v1(57.02,19.33) v1(57.02,18.03) v1(57.02,16.74) v1(57.12,27.89) v1(58.04,27.89) v1(58.04,26.33) v1(58.21,6.1) v1(58.21,4.78) v1(58.95,27.89) v1(58.95,26.33) v1(59.81,8.47) v1(59.81,7.38) v1(59.87,27.89) v1(59.87,26.33) v1(60.78,30.81) v1(60.78,27.89) v1(60.78,26.33) v1(61.4,8.47) v1(61.4,7.38) v1(62.01,20.31) v1(62.46,30.81) v1(62.46,27.31) v1(63.25,27.31) v1(63.23,20.31) v1(63.23,18.54) v1(64.03,30.81) v1(64.03,27.31) v1(64.39,5.97) v1(64.39,1.59) v1(64.45,20.31) v1(64.45,18.54) v1(64.45,16.78) v1(64.45,15.01) v1(64.45,13.25) v1(64.45,11.48) v1(64.45,9.72)
GND_ISO: length 78.4
  TOP w0.508: C30.2 37.08,40.61 37.08,41.02 ; C30.2 36.8,39.82 ; C30.2 37.33,40.33 ; C30.2 36.8,40.84 ; 13.75,39.8 D9.A ; D9.A 14.6,40.41 ; D9.A 15.46,39.8 ; D9.A 14.6,39.19 ; 13.28,35.69 T1.9 ; T1.9 13.28,38.08 ; T1.9 14.12,36.88 ; T1.9 12.45,36.88 ; C25.2 15.2,49.14 ; C25.2 14.4,50.42 ; C25.2 14.4,47.86 ; C25.2 13.6,49.14 ; T1.10 16.61,36.88 ; T1.10 15.77,35.69 ; T1.10 15.77,38.08 ; T1.10 14.94,36.88 ; 55.65,34.78 TEST.3 55.04,34.14 ; 14.4,44.6 C26.2 ; C26.2 13.6,45.88 ; C26.2 15.2,45.88 ; C26.2 14.4,47.16 ; C32.2 36.8,42.24 ; C32.2 36.8,41.22 ; C32.2 37.33,41.73 ; C35.2 31.11,48.84 ; C35.2 31.61,48.3 ; C35.2 30.6,48.3 ; C42.2 42.44,47.39 ; C42.2 41.91,46.9 ; C42.2 42.97,46.9 ; 13.6,42.62 C27.2 ; C27.2 14.4,43.9 ; C27.2 15.2,42.62 ; C27.2 14.4,41.33 ; 22.6,39.52 Y1.2 21.99,40.16 ; 46.14,40.83 U4.4 45.74,41.74 ; 24.22,41.52 Y1.4 23.61,42.16 ; 57.64,34.78 TEST.4 ; TEST.4 58.25,34.14 ; TEST.4 58.25,35.41 ; TEST.4 58.86,34.78 ; 33.35,36.43 C39.2 ; C39.2 32.84,36.96 ; C39.2 33.86,36.96 ; ALERT.C 55.84,42.87 ; ALERT.C 55.84,41.6 ; ALERT.C 55.11,42.24 ; C37.2 25.78,39.14 ; C37.2 25.27,38.61 ; C37.2 24.76,39.14 ; C40.2 37.05,39.09 ; C40.2 36.41,39.79 ; C40.2 36.41,38.39 ; 25.27,42.67 C36.2 24.76,42.13
  BOTTOM w0.508: R42.2 43.68,34.97 ; R42.2 43.68,33.67 ; R42.2 44.43,34.32 ; JP16.2 51.12,49.25 ; JP16.2 50.1,49.81 ; JP16.2 49.07,49.25 ; 37.82,34.79 D2.1 ; D2.1 39.52,34.79 ; D2.1 38.67,35.49 ; D2.1 38.67,34.1 ; 11.28,30.95 C24.2 ; C24.2 13.28,30.14 ; C24.2 15.29,30.95 ; C24.2 13.28,31.76 ; C33.2 36.3,38.38 ; C33.2 35.55,37.65 ; C33.2 34.8,38.38 ; C34.2 34.27,43.21 ; C34.2 32.77,43.21 ; C34.2 33.52,42.48 ; 32.77,38.38 C31.2 ; C31.2 34.27,38.38 ; C31.2 33.52,37.65 ; 43.56,41.07 R41.2 ; R41.2 43.56,42.37 ; R41.2 42.81,41.72 ; R41.2 44.31,41.72 ; 43.68,43.85 R40.2 43.68,42.56 ; 52.2,44.64 C43.2 51.62,45.19 ; C28.2 30.58,39.81 ; C28.2 30.07,40.34 ; C28.2 29.57,39.81 ; 47.17,34.03 U5.4 ; U5.4 47.17,36.73 ; U5.4 46.62,35.38 ; C29.2 31.36,40.82 ; C29.2 32.06,40.18 ; C29.2 30.66,40.18
  vias: v1(1.59,51.56) v1(1.59,47.36) v1(1.59,45.36) v1(1.59,43.37) v1(1.59,41.38) v1(1.59,39.38) v1(1.59,37.39) v1(1.59,35.39) v1(1.59,33.4) v1(1.59,31.41) v1(5.24,33.53) v1(7.36,33.53) v1(9.47,33.53) v1(12.28,32.25) v1(13.28,38.63) v1(13.28,32.25) v1(13.34,49.14) v1(14.11,40.87) v1(14.11,38.63) v1(14.29,32.25) v1(14.4,47.51) v1(14.94,40.87) v1(14.94,38.63) v1(15.77,46.31) v1(15.77,45.45) v1(15.77,43.05) v1(15.77,42.19) v1(15.77,38.63) v1(18.58,36.47) v1(18.96,49.14) v1(18.96,46.9) v1(20.65,49.14) v1(22.47,39.14) v1(22.79,42.54) v1(22.83,33.53) v1(23.11,39.14) v1(23.43,42.54) v1(23.74,39.14) v1(24.51,42.14) v1(24.46,39.14) v1(24.95,36.47) v1(24.95,33.53) v1(25.12,38.41) v1(28.33,46.28) v1(29.71,43.25) v1(29.71,42.49) v1(29.71,41.73) v1(29.71,40.97) v1(29.91,48.3) v1(30.47,43.25) v1(30.47,42.49) v1(30.47,41.73) v1(30.47,40.97) v1(31.24,43.25) v1(31.24,42.49) v1(31.24,41.73) v1(31.24,40.97) v1(32,43.25) v1(32,42.49) v1(32,41.73) v1(32,40.97) v1(32.02,47.6) v1(32.14,37.92) v1(33.02,36.22) v1(33.73,36.24) v1(34.57,38.18) v1(35.28,37.44) v1(35.83,37.44) v1(36.37,38.38) v1(37.74,42.3) v1(39.71,38.7) v1(39.71,38.06) v1(39.79,34.79) v1(41.38,41.24) v1(42.24,41.24) v1(42.44,47.65) v1(43.68,44.06) v1(43.68,32.98) v1(46.38,40.83) v1(47.17,37.19) v1(47.17,33.57) v1(48.44,37.92) v1(49.71,37.92) v1(50.1,50.25) v1(51.62,45.77) v1(52.11,40.83) v1(54.37,46.57) v1(54.37,44.96) v1(54.37,43.35) v1(55.52,33.96) v1(58.42,46.95) v1(58.42,45.68) v1(58.42,44.42) v1(58.9,34.06) v1(64.45,51.56) v1(64.45,47.45) v1(64.45,45.62) v1(64.45,43.79) v1(64.45,41.96) v1(64.45,40.13) v1(64.45,38.3) v1(64.45,36.47)
ADT75_OS: length 12.3
  TOP w0.203: v1(47.56,47.57) 47.56,39.92 46.94,39.3 R37.2 45.94,39.3 45.09,40.16 U4.3
  BOTTOM w0.203: v1(47.56,47.57) JP13.1
BUTTON_IO: length 28.3
  BOTTOM w0.203: BTN_IO.1 60.72,35.12 R47.1 ; R47.1 57.39,34.25 56.54,33.4 53.98,33.4 53.09,34.29 53.09,48.23 52.88,48.43 JP14.1 ; R47.1 R46.2
CS_N: length 15
  TOP w0.203: P3.24 38.28,53.05 38.28,48.14 37.9,47.76 35.81,47.76 35.57,47.52 R27.2 34.77,45.92 34.48,45.63 34.48,44.08 34.26,43.86 U3.29
DIFF_N: length 2.5
  TOP w0.203: v1(40.01,14.9) v1(40.01,14.37)
  BOTTOM w0.762: C3.1 37.09,20.94 R5.1
  vias: v1(40.54,14.9) v1(40.54,14.37)
DIFF_P: length 2
  BOTTOM w0.762: C2.1 30.69,20.94 R4.1
  vias: v1(40.01,12.36) v1(40.01,11.83) v1(40.54,12.36) v1(40.54,11.83)
EEPROM_SCL: length 18.1
  BOTTOM w0.203: U5.6 R43.2 47.88,43.29 47.62,43.55 47.62,45.72 47.18,46.16 46.23,46.16 45.91,46.48 45.91,48.58 45.28,49.21 44.26,49.21 43.24,50.23 43.24,53.18 P3.28
EEPROM_SDA: length 15.7
  BOTTOM w0.203: U5.5 47.17,41.67 46.51,42.33 46.51,43.29 ; 46.51,43.29 R45.2 ; 46.51,43.29 46.98,43.29 47.24,43.56 47.24,45.57 47.03,45.78 46.07,45.78 45.47,46.39 45.47,48.39 45.09,48.77 44.07,48.77 42.73,50.11 42.73,51.15 P3.27
I2C_SCL: length 56.1
  TOP w0.203: v1(17.53,31.31) 18.47,30.37 34.39,30.37 39.78,35.75 43.14,35.75 43.69,36.3 43.69,39.06 43.93,39.3 R38.2 44.44,39.33 U4.2
  BOTTOM w0.203: P3.5 17.53,48.41 v1(17.53,31.31)
I2C_SDA: length 55.3
  TOP w0.203: U4.1 43.79,40.1 42.99,39.3 R39.2 42.43,39.3 42.14,39.01 42.14,36.83 41.63,36.32 39.59,36.32 34.2,30.94 19.02,30.94 17.7,32.26 v1(16.57,32.26)
  BOTTOM w0.203: v1(16.57,32.26) 16.57,46.83 P3.3
INT_N: length 19
  TOP w0.203: v1(38.28,43.89) 38.22,43.82 36.26,43.82 R28.2 34.9,42.46 34.9,42.16 34.6,41.86 U3.25
  BOTTOM w0.203: P3.22 34.39,54.38 35.62,53.16 37.9,53.16 38.28,52.78 v1(38.28,43.89)
LED_IO: length 14.8
  BOTTOM w0.203: JP15.2 55.45,48.43 55.65,48.23 55.65,42.48 R48.1 56.71,43.05 60.39,43.05 LED_IO.1
LINK_ST: length 12.9
  TOP w0.203: U3.4 27.4,42.86 26.95,43.31 26.45,43.31 25.83,43.93 25.83,44.55 25.38,45.01 22.52,45.01 v1(21.86,45.67)
  BOTTOM w0.203: v1(21.86,45.67) 23.44,45.67 25.58,47.81 JP10.1
LT8304_EN: length 4
  BOTTOM w0.508: R21.1 9.37,12.95 7.59,14.73 U2.1
LT8304_VIN: length 25.5
  TOP w0.254: U1.11 20.57,21.04 20.06,20.53
  TOP w0.508: 20.06,20.53 20.06,18.65 C13.2 15.3,13.91 15.3,13.28 R20.1
  BOTTOM w0.508: 3.94,21.02 3.94,22.4 ; 3.94,21.02 3.94,19.63 ; 3.94,21.02 2.6,21.02 ; 3.94,21.02 5.27,21.02 ; 5.41,17.27 U2.3 ; U2.3 6.77,16.76 ; U2.3 6.77,17.78 ; 6.83,9.23 C15.1 ; C15.1 7.8,10.05 ; C15.1 8.78,9.23 ; 6.89,21.07 C22.1 6.17,20.32 ; 10.51,9.23 C14.1 ; C14.1 11.49,10.05 ; C14.1 12.47,9.23
  vias: v1(3.78,18.54) v1(3.78,17.91) v1(3.78,17.27) v1(4.42,18.54) v1(4.42,17.91) v1(7.45,11.85) v1(7.45,11.09) v1(8.22,11.85) v1(8.22,11.09) v1(8.98,11.85) v1(8.98,11.09)
LTC9111_STBY: length 38.5
  TOP w0.203: JP2.1 JP1.1 ; U1.4 25.67,22.04 C17.1 v1(26.18,24.58)
  L3 PWR w0.203: JP1.1 36.88,4.89 36.88,21.74 34.04,24.58 v1(26.18,24.58)
PD_IN1: length 7.8
  TOP w0.254: U1.1 24.36,20.54 24.76,20.15 v1(24.76,19.5)
  TOP w0.508: v1(33.56,16.89) 33.56,16.89 33.56,17.42 v1(33.56,17.42) 33.46,17.42 33.28,17.6
  TOP w0.762: Q4.8 32.44,16.3 32.45,16.3 D3.A 33.28,17.6
  BOTTOM w0.508: 34.09,16.89 v1(34.09,16.89) v1(33.56,16.89) v1(33.56,17.42) v1(34.09,17.42) 34.09,17.42 33.99,17.32 33.99,16.99 34.09,16.89
PD_IN2: length 6
  TOP w0.254: U1.2 24.87,21.04 ; 24.87,21.04 25.02,20.9 v1(25.2,20.9) 25.06,21.04 24.87,21.04
  TOP w0.508: 33.38,8.84 33.46,8.91 33.46,9.04 33.56,9.14 v1(33.55,9.14) 33.55,9.15 33.46,9.24 33.46,9.57 33.56,9.67 v1(33.55,9.67)
  TOP w0.762: 33.38,8.84 32.58,8.84 D4.A 32.45,10.14 32.16,10.43 Q4.5
  vias: v1(34.09,9.67) v1(34.09,9.14)
RESET_N: length 13.7
  TOP w0.203: v1(20.65,45.67) 21.71,44.6 25.06,44.6 25.26,44.4 R26.2 25.26,43.76 25.46,43.56 25.66,43.56 26.3,42.93 26.61,42.93 27.18,42.36 U3.5
  BOTTOM w0.203: v1(20.65,45.67) 20.65,46.45 21.01,46.81 22.54,46.81 23.04,47.32 JP9.1
RXN: length 6.6
  TOP w0.203: R13.2 29.13,34.58 29.13,36.73 28.93,36.93 28.46,36.93 R12.2 28.5,37.25 28.5,37.54 28.7,37.74 28.98,37.74 29.27,38.04 29.27,38.35 29.61,38.69 U3.13
RXP: length 6.3
  TOP w0.203: 30.35,37.07 30.23,37.2 30.23,37.59 29.8,38.02 29.8,38.31 30.11,38.61 U3.14 ; 30.35,37.07 R10.2 ; 30.35,37.07 30.21,36.93 29.77,36.93 29.51,36.68 29.51,34.61 R14.1
SCLK: length 14.1
  TOP w0.203: P3.23 35.24,50.17 35.24,50.17 31.68,50.17 30.86,49.35 29.08,49.35 28.38,48.65 28.34,48.57 28.34,47.1 28.53,46.91 29.61,45.83 U3.38
SDI: length 10.8
  TOP w0.203: U3.1 27.72,44.36 27.17,44.9 27.17,48.78 28.63,50.24 30.22,50.24 P3.19
SDO/SPI_CFG0: length 22.9
  TOP w0.203: v1(25.76,45.68) 27.58,43.86 U3.2
  BOTTOM w0.203: JP4.1 24.5,44.41 v1(25.76,45.68) 27,46.91 33.71,46.91 34.39,47.6 P3.21
SPI_CFG1: length 21.8
  TOP w0.203: U3.37 30.1,45.01 v1(30.1,46.33)
  BOTTOM w0.203: JP5.1 21.01,33.46 21.56,34.01 21.56,40.77 22.2,41.4 24.79,41.4 25.27,41.88 25.27,43.74 27.18,45.64 29.41,45.64 v1(30.1,46.33)
SWPD_ENB: length 9.8
  TOP w0.203: U3.33 32.11,45.71 32.77,46.37 32.77,48.91 33.01,49.16 v1(37.08,49.16)
  BOTTOM w0.203: v1(37.08,49.16) 35.96,49.16 JP3.1
TS_CAPT: length 4.4
  TOP w0.203: v1(27.74,47.51) 27.74,45.35 28.09,45 U3.40
  BOTTOM w0.203: JP11.2 27.95,48.43 27.74,48.23 v1(27.74,47.51)
TS_TIMER/MS_SEL: length 6
  TOP w0.203: v1(33.46,48.46) 33.75,48.17 U3.30
  BOTTOM w0.203: JP12.2 31.71,48.46 v1(33.46,48.46)
TVS_VCC: length 4.2
  BOTTOM w0.508: D2.4 38.58,36.78 37.3,38.06 C8.1 37.3,38.48 37.52,38.7 37.52,39.71 R8.2
TXN: length 12
  TOP w0.203: R14.2 30.04,33.12 29.83,33.32 26.7,33.32 26.2,33.82 26.2,36.82 26.45,37.07 R11.2 27.05,37.44 27.41,37.8 28.12,37.8 29.11,38.78 U3.12
TXP: length 11.1
  TOP w0.203: R9.2 31.46,37.07 30.61,37.93 v1(30.61,38.06) 30.61,38.16 30.61,38.17 U3.15 ; R13.1 v1(27.58,32.59)
  BOTTOM w0.203: v1(27.58,32.59) 28.62,32.59 30.61,34.57 v1(30.61,38.06)
UNNAMED_3_CAP_I52_N2: length 1.5
  BOTTOM w0.508: C22.2 R24.1
UNNAMED_3_CAP_I56_N1: length 2.7
  TOP w0.381: C23.1 v1(5.03,16.13)
  BOTTOM w0.203: U2.2 6.64,16.13 v1(5.03,16.13)
UNNAMED_3_DIO_I55_N: length 4.1
  BOTTOM w0.508: D7.C 7.87,25.41 D6.C
UNNAMED_3_DIO_I55_P: length 12.7
  TOP w0.508: 10.79,20.52 v1(10.79,22)
  BOTTOM w0.203: U2.5 16.11,18.54 R25.1
  BOTTOM w0.508: D7.A 10.32,22.47 v1(10.79,22) 11.71,21.08 R24.2 11.71,19.05 12.22,18.54 U2.5
UNNAMED_3_DIOSCHOTTKY3P_I49_A1: length 2.9
  TOP w1.143: T1.7 8.31,39.52 D8.1
UNNAMED_3_DIOSCHOTTKY3P_I49_A2: length 2.9
  TOP w1.143: D8.2 5.82,39.55 T1.6
UNNAMED_3_LINLT8304_I62_RFB: length 3.9
  BOTTOM w0.203: R25.2 16.11,17.27 U2.6
UNNAMED_3_LINLT8304_I62_RREF: length 3.8
  BOTTOM w0.203: U2.7 14.41,16 R22.2 R23.1
UNNAMED_3_LINLT8304_I62_TC: length 2.7
  BOTTOM w0.203: R22.1 14.18,14.73 U2.8
UNNAMED_6_CMOSCAT24CXX_I92_WP: length 9.3
  BOTTOM w0.203: U5.7 49.71,41.96 49.97,42.21 R44.2 50.55,43.29 50.75,43.5 50.75,48.23 50.55,48.43 JP16.1
UNNAMED_6_CN40PV2_I2_N8: length 5.7
  BOTTOM w0.203: JP11.1 28,49.37 28,53.18 P3.16
UNNAMED_6_CN40PV2_I2_N9: length 6.6
  BOTTOM w0.203: JP12.1 30.81,49.25 30.54,49.52 30.54,53.18 P3.18
UNNAMED_6_CN40PV2_I2_N18: length 6.2
  BOTTOM w0.203: P3.36 53.37,53.21 53.37,49.61 53.01,49.25 JP14.2
UNNAMED_6_CN40PV2_I3_N7: length 3.4
  BOTTOM w0.203: P3.13 24.23,49.9 23.58,49.25 JP9.2
UNNAMED_6_CN40PV2_I3_N8: length 3.3
  BOTTOM w0.203: JP10.2 25.99,49.25 26.77,50.03 P3.15
UNNAMED_6_CN40PV2_I3_N16: length 3
  BOTTOM w0.203: P3.31 47.09,49.45 47.3,49.25 JP13.2
UNNAMED_6_CN40PV2_I3_N19: length 2.9
  BOTTOM w0.203: P3.37 54.71,49.5 54.97,49.25 JP15.1
UNNAMED_6_DIOLED_I156_P: length 2
  TOP w0.203: ALERT.A v1(58.42,42.24)
  BOTTOM w0.203: R48.2 v1(58.42,42.24)
UNNAMED_6_RES_I163_N2: length 5.1
  TOP w0.203: TEST.2 TEST.1 55.04,35.61 v1(55.04,35.61)
  BOTTOM w0.203: R47.2 55.52,35.12 v1(55.04,35.61)
UNNAMED_8_CAP_I59_N2: length 5
  BOTTOM w0.762: L3.3 32.61,22.88 C2.2 32.33,22.53 30.75,22.53 R4.2
UNNAMED_8_CAP_I60_N2: length 5
  BOTTOM w0.762: R5.2 37.01,22.5 35.47,22.5 C3.2 35.11,22.87 L3.2
UNNAMED_8_CAP_I64_N1: length 40.5
  TOP w0.457: C4.1 54.2,26.5 54.66,26.04 R2.1 53.84,25.04 v1(53.16,24.36) ; v1(53.16,20.5) 53.16,9.34 P2.1
  L2 GND w0.457: v1(53.16,20.5) v1(53.16,24.36)
  BOTTOM w0.889: P1.1 61.47,11.37 D1.1 56.75,8.88 P2.1 51.62,6.88 49,6.88 45.7,10.18 L1.4
UNNAMED_8_CAP_I66_N1: length 9.3
  TOP w1.016: R6.1 61.56,23.77 60.67,22.87 C5.1 57.49,22.87 56.78,22.16 R2.2
UNNAMED_8_CAP_I70_N1: length 9.2
  TOP w1.016: R3.2 48.25,22.18 47.56,22.87 C6.1 43.32,22.87 42.42,23.77 R7.1
UNNAMED_8_CAP_I71_N1: length 44.2
  TOP w0.457: v1(51.88,24.35) 51.16,25.06 R3.1 50.34,26.04 50.8,26.5 C7.1 ; P2.2 51.88,9.94 v1(51.88,20.52)
  L2 GND w0.457: v1(51.88,20.52) v1(51.88,24.35)
  BOTTOM w0.889: P1.2 61.47,13.97 D1.2 59.23,13.97 53.47,13.97 52.02,12.52 52.02,9.78 51.12,8.88 P2.2 50.62,9.08 50.62,13.34 49.32,14.64 L1.3
UNNAMED_8_CAP_I91_N1: length 47
  L3 PWR w0.889: P2.GND4 P2.GND3 47.77,10.83 P2.GND2 P2.GND1 56.02,12.79 59.72,16.48 P1.3
  BOTTOM w1.016: P1.3 59.54,18.45 C1.1 60.01,23.34 62,23.34 63.26,24.61 R1.1
UNNAMED_8_DIO4PV7_I21_I: length 16.2
  TOP w0.203: v1(27.14,34.75) 27.05,34.84 R11.1 R12.1
  L3 PWR w0.254: v1(35.1,34.91) 35.1,33.64 34.35,32.89 28.99,32.89 v1(27.14,34.75)
  BOTTOM w0.254: L3.1 35.11,34.91 v1(35.1,34.91) 35.69,34.91 35.81,34.79 D2.2
UNNAMED_8_DIO4PV7_I21_I_1: length 9.5
  TOP w0.203: R10.1 R9.1 32.28,34.91 v1(32.61,34.91)
  BOTTOM w0.254: L3.4 v1(32.61,34.91) 33.88,34.91 35.75,36.78 D2.3
UNNAMED_9_ADLTC9111_I40_CLASSC: length 24.2
  TOP w0.203: U1.10 v1(19.56,21.54)
  L3 PWR w0.203: JP2.2 19.56,13.88 v1(19.56,21.54)
UNNAMED_9_ADLTC9111_I40_CLASSV: length 35.2
  TOP w0.203: v1(25.02,24.58) 25.02,22.86 24.7,22.54 U1.5
  L3 PWR w0.203: v1(25.02,24.58) 25.58,25.14 34.04,25.14 37.48,21.7 37.48,3.5 JP1.2
UNNAMED_9_ADLTC9111_I40_EN: length 22.3
  TOP w0.203: v1(23.98,24.58) 24.12,24.44 U1.6
  BOTTOM w0.203: R21.2 11.92,12.75 16.84,12.75 17.32,13.23 17.32,16.15 20.75,19.58 20.75,22.5 22.88,24.63 23.37,24.63 23.42,24.58 v1(23.98,24.58)
UNNAMED_9_ADLTC9111_I40_GATE: length 15.9
  TOP w0.254: C13.1 21.2,18.78 U1.12
  TOP w0.508: v1(21.5,17.54) C13.1
  BOTTOM w0.381: v1(21.5,17.54) 21.5,14.69 20.79,13.98 R19.1 19.8,12.43 19.23,11.86 14.89,11.86 14.41,11.38 Q1.4
UNNAMED_9_ADLTC9111_I40_LGATE1: length 21.4
  TOP w0.203: Q4.2 25.35,13.92 23.57,15.69 v1(22.89,15.69) ; v1(20.38,25.73) 19.74,25.09 19.74,22.55 20.25,22.04 U1.9
  L3 PWR w0.203: v1(22.89,15.69) 22.15,15.69 20.75,17.09 20.75,17.65 21.08,17.98 21.08,25.02 v1(20.38,25.73)
